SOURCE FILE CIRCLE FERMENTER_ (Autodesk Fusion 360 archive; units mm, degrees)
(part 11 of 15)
sketch "Schizzo6" plane through (170, 0, 0) normal (1, 0, 0) x axis (0, 1, 0)
  line L1 (-85.9, 154.9) -> (-85.9, 164.9)
  curve K1 (-65, 134) -> (-85.9, 154.9)
  line L2 (65, 134) -> (-65, 134)
  curve K2 (85.9, 154.9) -> (65, 134)
  line L3 (85.9, 164.9) -> (85.9, 154.9)
  curve K3 (85.9, 164.9) -> (65, 185.8)
  line L4 (-65, 185.8) -> (65, 185.8)
  curve K4 (-65, 185.8) -> (-85.9, 164.9)
  line L5 (-22.5, 172.4) -> (-72.5, 172.4)
  line L6 (-22.5, 147.4) -> (-22.5, 172.4)
  line L7 (-72.5, 147.4) -> (-22.5, 147.4)
  line L8 (-72.5, 172.4) -> (-72.5, 147.4)
  line L9 (-77.9, 164.9) -> (-77.9, 154.9)
  line L10 (65, 177.8) -> (-65, 177.8)
  line L11 (65, 142) -> (-65, 142)
  line L12 (-77.9, 159.9) -> (-22.5, 159.9)
  curve K5 (-65, 177.8) -> (-77.9, 164.9)
  line L13 (-47.5, 147.4) -> (-47.5, 172.4)
  curve K6 (-71.9336, 172.3394) -> (-71.9423, 172.3232)
  line L14 (-72.5, 164.9) -> (-72.5, 154.9)
  curve K7 (-72.0707, 171.9774) -> (-72.5, 164.9)
  curve K8 (-65, 172.4) -> (-72.0707, 171.9774)
  line L15 (65, 172.4) -> (-65, 172.4)
  curve K9 (-22.9293, 171.9774) -> (-22.5, 164.9)
  curve K10 (-30, 172.4) -> (-22.9293, 171.9774)
  curve K11 (-72.0707, 147.8226) -> (-72.5, 154.9)
  curve K12 (-65, 147.4) -> (-72.0707, 147.8226)
  curve K13 (-30, 147.4) -> (-22.9293, 147.8226)
  curve K14 (-22.9293, 147.8226) -> (-22.5, 154.9)
  circle C1 centre (60, 159.9) radius 3.5
  circle C2 centre (81.9, 159.9) radius 1.75
  circle C3 centre (0, 181.8) radius 1.75
  circle C4 centre (0, 138) radius 1.75
  circle C5 centre (-81.9, 159.9) radius 1.75
  point P25 (-22.5, 159.9)
  point P26 (-77.9, 159.9)
  point P34 (-47.5, 172.4)
  point P35 (-47.5, 147.4)
  point P30 (-72.5, 164.9)
  point P36 (-22.5, 164.9)
  point P31 (-72.0707, 171.9774)
  point P37 (-22.9293, 171.9774)
  point P32 (-65, 172.4)
  point P38 (-30, 172.4)
  point P39 (-72.5, 154.9)
  point P40 (-72.0707, 147.8226)
  point P41 (-65, 147.4)
  point P44 (-22.5, 154.9)
  point P42 (-22.9293, 147.8226)
  point P43 (-30, 147.4)
  point P16 (-22.5, 172.4)
  point P17 (-22.5, 147.4)
  horizontal L5
  vertical L6
  horizontal L7
  vertical L8
  midpoint L6 P25
  midpoint L9 P26
  horizontal L12
  midpoint L5 P34
  midpoint L7 P35
  symmetric P30 L13 P36
  symmetric P31 L13 P37
  symmetric P32 L13 P38
  symmetric L13 K7 K9
  symmetric L13 K8 K10
  symmetric L12 P30 P39
  symmetric L12 P31 P40
  symmetric L12 P32 P41
  symmetric L12 K7 K11
  symmetric L12 K8 K12
  symmetric L12 P36 P44
  symmetric L12 P37 P42
  symmetric L12 K9 K14
  symmetric L12 P38 P43
  symmetric L12 K10 K13
  dimension "d1506" distance P16 P17 = 25
  dimension "d1507" distance L6 L8 = 50
  dimension "d1508" distance L8 L9 = 5.4
  dimension "d1509" = 5.4
extrude "Estrusione3" cut sketch "Schizzo6" profile of L5 L6 L7 L8 K8 L14 L15 K9 K10 K11 K12 K13 K14 against normal blind 3
fillet "Raccordo1" radius 4
component_insert "Inserimento componente1"
joint "Assembla1" alignAngle 0 alignOffsetX 0 alignOffsetY -12.5 alignOffsetZ 0
offset_faces "FacceDiOffset1" distance 0.5
sketch "Schizzo6" plane through (170, 0, 0) normal (1, 0, 0) x axis (0, 1, 0)
  curve K1 (-71.9729, 151.8273) -> (-72, 154.9)
  line L1 (-72, 164.9) -> (-72, 154.9)
  curve K2 (-72, 164.9) -> (-71.9729, 167.9727)
  curve K3 (-71.9729, 167.9727) -> (-68.0604, 171.8773)
  curve K4 (-68.0604, 171.8773) -> (-65, 171.9)
  line L2 (-30, 171.9) -> (-65, 171.9)
  curve K5 (-30, 171.9) -> (-26.9396, 171.8773)
  curve K6 (-26.9396, 171.8773) -> (-23.0271, 167.9727)
  curve K7 (-23.0271, 167.9727) -> (-23, 164.9)
  line L3 (-23, 154.9) -> (-23, 164.9)
  curve K8 (-23, 154.9) -> (-23.0271, 151.8273)
  curve K9 (-23.0271, 151.8273) -> (-26.9396, 147.9227)
  curve K10 (-26.9396, 147.9227) -> (-30, 147.9)
  line L4 (-65, 147.9) -> (-30, 147.9)
  curve K11 (-65, 147.9) -> (-68.0604, 147.9227)
  curve K12 (-68.0604, 147.9227) -> (-71.9729, 151.8273)
  line L5 (-85.9, 154.9) -> (-85.9, 164.9)
  curve K13 (-65, 134) -> (-85.9, 154.9)
  line L6 (65, 134) -> (-65, 134)
  curve K14 (85.9, 154.9) -> (65, 134)
  line L7 (85.9, 164.9) -> (85.9, 154.9)
  curve K15 (85.9, 164.9) -> (65, 185.8)
  line L8 (-65, 185.8) -> (65, 185.8)
  curve K16 (-65, 185.8) -> (-85.9, 164.9)
  line L9 (42.523, 154.9) -> (42.523, 164.9)
  line L10 (-23, 154.9) -> (-23, 164.9)
  line L11 (42.523, 159.9) -> (-23, 159.9)
  circle C1 centre (60, 159.9) radius 3.5
  circle C2 centre (81.9, 159.9) radius 1.75
  circle C3 centre (0, 181.8) radius 1.75
  circle C4 centre (0, 138) radius 1.75
  circle C5 centre (-81.9, 159.9) radius 1.75
  circle C6 centre (-5.2385, 159.9) radius 2.5
  circle C7 centre (9.7615, 159.9) radius 2.5
  circle C8 centre (24.7615, 159.9) radius 2.5
  point P35 (-23, 159.9)
  point P36 (42.523, 159.9)
  point P37 (9.7615, 159.9)
  point P38 (-5.2385, 159.9)
  point P39 (24.7615, 159.9)
  point P40 (-5.2385, 159.9)
  point P41 (9.7615, 159.9)
  point P42 (24.7615, 159.9)
  midpoint L3 P35
  midpoint L9 P36
  midpoint L11 P37
  coincident L11 P38
  coincident L11 P39
  coincident P38 P40
  coincident P37 P41
  coincident P39 P42
  dimension "d1519" distance P37 P38 = 15
  dimension "d1520" distance P37 P39 = 15
  dimension "d1521" diameter C6 = 5
  dimension "d1522" diameter C7 = 5
  dimension "d1523" diameter C8 = 5
extrude "Estrusione4" cut sketch "Schizzo6" profile of C6 C7 C8 against normal blind 3
sketch "Schizzo7" plane through (164, 0, 0) normal (-1, 0, 0) x axis (0, 0, 1)
  line L1 (140.05, -73.65) -> (140.05, -16.65)
  line L2 (177.75, -75.65) -> (142.05, -75.65)
  line L3 (179.75, -16.65) -> (179.75, -73.65)
  line L4 (142.05, -14.65) -> (177.75, -14.65)
  curve K1 (141.3132, 79.0124) -> (139.6916, 76.9033)
  curve K2 (154.9, 81.9) -> (141.3132, 79.0124)
  line L5 (156.9, 81.9) -> (154.9, 81.9)
  line L6 (164.9, 81.9) -> (162.9, 81.9)
  curve K3 (178.4868, 79.0124) -> (164.9, 81.9)
  curve K4 (180.1083, 76.9033) -> (178.4868, 79.0124)
  curve K5 (181.8, 65) -> (180.1083, 76.9033)
  line L7 (181.8, 3) -> (181.8, 65)
  line L8 (181.8, -65) -> (181.8, -3)
  curve K6 (181.2771, -73.5898) -> (181.8, -65)
  curve K7 (179.0826, -78.3954) -> (181.2771, -73.5898)
  curve K8 (164.9, -81.9) -> (179.0826, -78.3954)
  line L9 (162.9, -81.9) -> (164.9, -81.9)
  line L10 (154.9, -81.9) -> (156.9, -81.9)
  curve K9 (140.7174, -78.3954) -> (154.9, -81.9)
  curve K10 (138.5229, -73.5898) -> (140.7174, -78.3954)
  curve K11 (138, -65) -> (138.5229, -73.5898)
  line L11 (138, -3) -> (138, -65)
  line L12 (138, 65) -> (138, 3)
  curve K12 (139.6916, 76.9033) -> (138, 65)
  curve K13 (134.6069, -74.4055) -> (134, -65)
  curve K14 (137.6898, -81.0094) -> (134.6069, -74.4055)
  curve K15 (154.9, -85.9) -> (137.6898, -81.0094)
  line L13 (164.9, -85.9) -> (154.9, -85.9)
  curve K16 (182.1102, -81.0094) -> (164.9, -85.9)
  curve K17 (185.1931, -74.4056) -> (182.1102, -81.0094)
  curve K18 (185.8, -65) -> (185.1931, -74.4056)
  line L14 (185.8, 65) -> (185.8, -65)
  curve K19 (183.6203, 78.818) -> (185.8, 65)
  curve K20 (181.2032, 81.9485) -> (183.6203, 78.818)
  curve K21 (164.9, 85.9) -> (181.2032, 81.9485)
  line L15 (154.9, 85.9) -> (164.9, 85.9)
  curve K22 (138.5968, 81.9485) -> (154.9, 85.9)
  curve K23 (136.1797, 78.818) -> (138.5968, 81.9485)
  curve K24 (134, 65) -> (136.1797, 78.818)
  line L16 (134, -65) -> (134, 65)
  line L17 (144.6716, -75.65) -> (144.6716, -14.65)
  line L18 (175.5614, -75.65) -> (144.6716, -75.65)
  line L19 (175.5614, -14.65) -> (175.5614, -75.65)
  line L20 (144.6716, -14.65) -> (175.5614, -14.65)
  line L21 (181.8, -9.65) -> (138, -9.65)
  circle C1 centre (177.25, -73.15) radius 1
  circle C2 centre (177.25, -17.15) radius 1
  circle C3 centre (142.55, -17.15) radius 1
  circle C4 centre (142.55, -73.15) radius 1
  arc A1 centre (142.05, -16.65) radius 2 clockwise from (140.05, -16.65) to (142.05, -14.65)
  arc A2 centre (142.05, -73.65) radius 2 clockwise from (142.05, -75.65) to (140.05, -73.65)
  arc A3 centre (177.75, -73.65) radius 2 clockwise from (179.75, -73.65) to (177.75, -75.65)
  arc A4 centre (177.75, -16.65) radius 2 clockwise from (177.75, -14.65) to (179.75, -16.65)
  arc A5 centre (159.9, 81.9) radius 3 clockwise from (162.9, 81.9) to (156.9, 81.9)
  arc A6 centre (181.8, 0) radius 3 clockwise from (181.8, -3) to (181.8, 3)
  arc A7 centre (159.9, -81.9) radius 3 clockwise from (156.9, -81.9) to (162.9, -81.9)
  arc A8 centre (138, 0) radius 3 clockwise from (138, 3) to (138, -3)
  circle C5 centre (159.9, 81.9) radius 1.75
  circle C6 centre (159.9, -81.9) radius 1.75
  circle C7 centre (138, 0) radius 1.75
  circle C8 centre (181.8, 0) radius 1.75
  point P66 (138, -9.65)
  point P67 (181.8, -9.65)
  coincident L11 P66
  coincident L8 P67
  perpendicular L8 L21
  dimension "d1526" distance L4 L21 = 5
extrude "Estrusione5" new body sketch "Schizzo7" profile of A1 L1 A2 L2 A3 L3 A4 L4 L8 K6 K7 K8 L9 A7 L10 K9 K10 K11 L11 L18 L20 L21 to an object
combine "Combina1"
extrude "Estrusione6" new body of existing geometry blind 4
combine "Combina2"
sketch "Schizzo6" plane through (160, 0, 0) normal (-1, 0, 0) x axis (0, -1, 0)
  line L1 (14.65, 177.75) -> (14.65, 142.05)
  line L2 (73.65, 179.75) -> (16.65, 179.75)
  line L3 (75.65, 142.05) -> (75.65, 177.75)
  line L4 (16.65, 140.05) -> (73.65, 140.05)
  line L5 (9.65, 138) -> (9.65, 181.8)
  line L6 (3, 138) -> (9.65, 138)
  line L7 (-65, 138) -> (-3, 138)
  curve K1 (-76.9033, 139.6916) -> (-65, 138)
  curve K2 (-79.0124, 141.3132) -> (-76.9033, 139.6916)
  curve K3 (-81.9, 154.9) -> (-79.0124, 141.3132)
  line L8 (-81.9, 156.9) -> (-81.9, 154.9)
  line L9 (-81.9, 164.9) -> (-81.9, 162.9)
  curve K4 (-79.0124, 178.4868) -> (-81.9, 164.9)
  curve K5 (-76.9033, 180.1084) -> (-79.0124, 178.4868)
  curve K6 (-65, 181.8) -> (-76.9033, 180.1084)
  line L10 (-3, 181.8) -> (-65, 181.8)
  line L11 (9.65, 181.8) -> (3, 181.8)
  curve K7 (74.4055, 134.6069) -> (65, 134)
  curve K8 (81.0094, 137.6898) -> (74.4055, 134.6069)
  curve K9 (85.9, 154.9) -> (81.0094, 137.6898)
  line L12 (85.9, 164.9) -> (85.9, 154.9)
  curve K10 (81.0094, 182.1102) -> (85.9, 164.9)
  curve K11 (74.4056, 185.1931) -> (81.0094, 182.1102)
  curve K12 (65, 185.8) -> (74.4056, 185.1931)
  line L13 (-65, 185.8) -> (65, 185.8)
  curve K13 (-78.818, 183.6203) -> (-65, 185.8)
  curve K14 (-81.9485, 181.2032) -> (-78.818, 183.6203)
  curve K15 (-85.9, 164.9) -> (-81.9485, 181.2032)
  line L14 (-85.9, 154.9) -> (-85.9, 164.9)
  curve K16 (-81.9485, 138.5968) -> (-85.9, 154.9)
  curve K17 (-78.818, 136.1797) -> (-81.9485, 138.5968)
  curve K18 (-65, 134) -> (-78.818, 136.1797)
  line L15 (65, 134) -> (-65, 134)
  line L16 (14.65, 142.05) -> (75.65, 142.05)
  line L17 (74.4679, 177.75) -> (75.65, 177.75)
  line L18 (14.65, 177.75) -> (74.4679, 177.75)
  arc A1 centre (16.65, 177.75) radius 2 clockwise from (14.65, 177.75) to (16.65, 179.75)
  arc A2 centre (73.65, 177.75) radius 2 clockwise from (73.65, 179.75) to (75.65, 177.75)
  arc A3 centre (73.65, 142.05) radius 2 clockwise from (75.65, 142.05) to (73.65, 140.05)
  arc A4 centre (16.65, 142.05) radius 2 clockwise from (16.65, 140.05) to (14.65, 142.05)
  arc A5 centre (0, 138) radius 3 clockwise from (-3, 138) to (3, 138)
  arc A6 centre (-81.9, 159.9) radius 3 clockwise from (-81.9, 162.9) to (-81.9, 156.9)
  arc A7 centre (0, 181.8) radius 3 clockwise from (3, 181.8) to (-3, 181.8)
  circle C1 centre (-81.9, 159.9) radius 1.75
  circle C2 centre (81.9, 159.9) radius 1.75
  circle C3 centre (0, 138) radius 1.75
  circle C4 centre (0, 181.8) radius 1.75
  point P9 (75.65, 142.05)
  point P50 (75.65, 142.05)
  point P2 (14.65, 142.05)
  point P51 (14.65, 142.05)
  point P7 (75.65, 177.75)
  point P52 (75.65, 177.75)
  point P3 (14.65, 177.75)
  point P54 (14.65, 177.75)
  coincident P9 P50
  coincident P2 P51
  coincident P7 P52
  perpendicular L1 L17
  coincident P3 P54
extrude "Estrusione4" new body sketch "Schizzo6" profile of A1 L2 A2 A3 L4 A4 L16 L17 L18 against normal blind 3.8
combine "Combina3"
offset_faces "FacceDiOffset1" distance -0.2
fillet "Raccordo1" radius 1 2 2
fillet "Raccordo2" radius 1
sketch "Schizzo1" plane through (160, 0, 0) normal (-1, 0, 0) x axis (0, -1, 0)
  curve K1 (86.4, 164.9) -> (65, 186.3)
  line L1 (86.4, 154.9) -> (86.4, 164.9)
  curve K2 (65, 133.5) -> (86.4, 154.9)
  line L2 (-65, 133.5) -> (65, 133.5)
  curve K3 (-86.4, 154.9) -> (-65, 133.5)
  line L3 (-86.4, 164.9) -> (-86.4, 154.9)
  curve K4 (-65, 186.3) -> (-86.4, 164.9)
  line L4 (65, 186.3) -> (-65, 186.3)
  line L5 (-89.2, 154.9) -> (-89.2, 164.9)
  curve K5 (-89.2, 154.9) -> (-65, 130.7)
  line L6 (65, 130.7) -> (-65, 130.7)
  curve K6 (65, 130.7) -> (89.2, 154.9)
  line L7 (89.2, 164.9) -> (89.2, 154.9)
  curve K7 (65, 189.1) -> (89.2, 164.9)
  line L8 (-65, 189.1) -> (65, 189.1)
  curve K8 (-89.2, 164.9) -> (-65, 189.1)
  curve K9 (90, 154.9) -> (65, 129.9)
  line L9 (90, 164.9) -> (90, 154.9)
  curve K10 (90, 164.9) -> (65, 189.9)
  line L10 (65, 189.9) -> (-65, 189.9)
  curve K11 (-65, 189.9) -> (-90, 164.9)
  line L11 (-90, 154.9) -> (-90, 164.9)
  curve K12 (-65, 129.9) -> (-90, 154.9)
  line L12 (65, 129.9) -> (-65, 129.9)
  line L13 (88.4, 164.9) -> (88.4, 154.9)
  curve K13 (88.4, 164.9) -> (65, 188.3)
  line L14 (65, 188.3) -> (-65, 188.3)
  curve K14 (-65, 188.3) -> (-88.4, 164.9)
  line L15 (-88.4, 154.9) -> (-88.4, 164.9)
  curve K15 (-65, 131.5) -> (-88.4, 154.9)
  line L16 (65, 131.5) -> (-65, 131.5)
  curve K16 (88.4, 154.9) -> (65, 131.5)
  dimension "d1542" = 1.6
extrude "Estrusione1" new body sketch "Schizzo1" profile of L5 K5 L6 K6 L7 K7 L8 K8 K9 L9 K10 L10 K11 L11 K12 L12 K13 L13 K16 L14 K15 K14 L15 L16 along normal blind 160
work_plane "Piano di lavoro1"
split "Dividi1"
remove_body "RimuoviCorpo1"
work_plane "Piano di lavoro2"
split "Dividi2"
remove_body "RimuoviCorpo2"
sketch "Schizzo7" plane through (0, 0, 0) normal (0, 1, 0) x axis (-1, 0, 0)
  line L1 (0, 131.5) -> (0, 129.9)
  line L2 (-160, 131.5) -> (0, 131.5)
  line L3 (-160, 129.9) -> (-160, 131.5)
  line L4 (0, 129.9) -> (-160, 129.9)
  line L5 (-160, 164.9) -> (-160, 186.3)
  line L6 (-160, 154.9) -> (-160, 164.9)
  line L7 (-160, 133.5) -> (-160, 154.9)
  line L8 (-160, 154.9) -> (-160, 133.5)
  line L9 (-160, 164.9) -> (-160, 154.9)
  line L10 (-160, 186.3) -> (-160, 164.9)
  line L11 (-160, 154.9) -> (-160, 164.9)
  line L12 (-160, 154.9) -> (-160, 130.7)
  line L13 (-160, 130.7) -> (-160, 154.9)
  line L14 (-160, 164.9) -> (-160, 154.9)
  line L15 (-160, 189.1) -> (-160, 164.9)
  line L16 (-160, 164.9) -> (-160, 189.1)
  line L17 (-160, 176.75) -> (-160, 143.05)
  line L18 (-160, 177.75) -> (-160, 176.75)
  line L19 (-160, 177.75) -> (-160, 176.75)
  line L20 (-160, 143.05) -> (-160, 176.75)
  line L21 (-160, 143.05) -> (-160, 142.05)
  line L22 (-160, 143.05) -> (-160, 142.05)
  line L23 (-160, 140) -> (-160, 179.8)
  line L24 (-160, 140) -> (-160, 138)
  line L25 (-160, 138.75) -> (-160, 138)
  line L26 (-160, 141) -> (-160, 138.75)
  line L27 (-160, 138.75) -> (-160, 138)
  line L28 (-160, 139.6916) -> (-160, 138)
  line L29 (-160, 141.3132) -> (-160, 139.6916)
  line L30 (-160, 154.9) -> (-160, 141.3132)
  line L31 (-160, 156.027) -> (-160, 154.9)
  line L32 (-160, 156.9953) -> (-160, 156.027)
  line L33 (-160, 162.8047) -> (-160, 156.9953)
  line L34 (-160, 163.773) -> (-160, 162.8047)
  line L35 (-160, 164.9) -> (-160, 163.773)
  line L36 (-160, 178.4868) -> (-160, 164.9)
  line L37 (-160, 180.1084) -> (-160, 178.4868)
  line L38 (-160, 181.8) -> (-160, 180.1084)
  line L39 (-160, 181.8) -> (-160, 181.05)
  line L40 (-160, 181.05) -> (-160, 178.8)
  line L41 (-160, 181.8) -> (-160, 181.05)
  line L42 (-160, 181.8) -> (-160, 179.8)
  line L43 (-160, 158.15) -> (-160, 161.65)
  line L44 (-160, 158.15) -> (-160, 161.65)
  line L45 (-160, 136.25) -> (-160, 139.75)
  line L46 (-160, 180.05) -> (-160, 183.55)
  line L47 (-160, 134.6069) -> (-160, 134)
  line L48 (-160, 137.6898) -> (-160, 134.6069)
  line L49 (-160, 154.9) -> (-160, 137.6898)
  line L50 (-160, 164.9) -> (-160, 154.9)
  line L51 (-160, 182.1102) -> (-160, 164.9)
  line L52 (-160, 185.1931) -> (-160, 182.1102)
  line L53 (-160, 185.8) -> (-160, 185.1931)
  line L54 (-160, 183.6203) -> (-160, 185.8)
  line L55 (-160, 181.2032) -> (-160, 183.6203)
  line L56 (-160, 164.9) -> (-160, 181.2032)
  line L57 (-160, 154.9) -> (-160, 164.9)
  line L58 (-160, 138.5968) -> (-160, 154.9)
  line L59 (-160, 136.1797) -> (-160, 138.5968)
  line L60 (-160, 134) -> (-160, 136.1797)
  line L61 (-151.2986, 138) -> (-160, 138)
  curve K1 (-156, 138) -> (-160, 138)
  curve K2 (-152.5, 134.75) -> (-156, 138)
  curve K3 (-149, 131.5) -> (-152.5, 134.75)
  curve K4 (-145, 131.5) -> (-149, 131.5)
  curve K5 (-145, 131.5) -> (-160, 138)
  point P19 (-160, 138)
  point P51 (-160, 138)
  point P53 (-156, 138)
  point P55 (-149, 131.5)
  point P56 (-145, 131.5)
  coincident P19 P51
  perpendicular L13 L61
  coincident L61 P53
  coincident L2 P55
  coincident L2 P56
  equal K2 K3
  parallel K2 K3
  dimension "d1545" distance L2 L61 = 6.5
  dimension "d1546" distance P51 P53 = 4
  dimension "d1547" distance P55 P56 = 4 (= "d1546")
  dimension "d1548" distance P51 P56 = 15
sweep "Sweep1" sketch "Schizzo7" TwistAngle 0 TaperAngle 0
combine "Combina1"
sketch "Schizzo3" plane through (160, 0, 0) normal (-1, 0, 0) x axis (0, -1, 0)
  line L1 (14.45, 176.75) -> (14.45, 143.05)
  line L2 (74.85, 177.75) -> (15.45, 177.75)
  line L3 (75.85, 143.05) -> (75.85, 176.75)
  line L4 (15.45, 142.05) -> (74.85, 142.05)
  line L5 (9.65, 140) -> (9.65, 179.8)
  line L6 (3.873, 138) -> (7.65, 138)
  line L7 (-65, 138) -> (-3.873, 138)
  curve K1 (-76.9033, 139.6916) -> (-65, 138)
  curve K2 (-79.0124, 141.3132) -> (-76.9033, 139.6916)
  curve K3 (-81.9, 154.9) -> (-79.0124, 141.3132)
  line L8 (-81.9, 156.027) -> (-81.9, 154.9)
  line L9 (-81.9, 164.9) -> (-81.9, 163.773)
  curve K4 (-79.0124, 178.4868) -> (-81.9, 164.9)
  curve K5 (-76.9033, 180.1084) -> (-79.0124, 178.4868)
  curve K6 (-65, 181.8) -> (-76.9033, 180.1084)
  line L10 (-3.873, 181.8) -> (-65, 181.8)
  line L11 (7.65, 181.8) -> (3.873, 181.8)
  curve K7 (74.4055, 134.6069) -> (65, 134)
  curve K8 (81.0094, 137.6898) -> (74.4055, 134.6069)
  curve K9 (85.9, 154.9) -> (81.0094, 137.6898)
  line L12 (85.9, 164.9) -> (85.9, 154.9)
  curve K10 (81.0094, 182.1102) -> (85.9, 164.9)
  curve K11 (74.4056, 185.1931) -> (81.0094, 182.1102)
  curve K12 (65, 185.8) -> (74.4056, 185.1931)
  line L13 (-65, 185.8) -> (65, 185.8)
  curve K13 (-78.818, 183.6203) -> (-65, 185.8)
  curve K14 (-81.9485, 181.2032) -> (-78.818, 183.6203)
  curve K15 (-85.9, 164.9) -> (-81.9485, 181.2032)
  line L14 (-85.9, 154.9) -> (-85.9, 164.9)
  curve K16 (-81.9485, 138.5968) -> (-85.9, 154.9)
  curve K17 (-78.818, 136.1797) -> (-81.9485, 138.5968)
  curve K18 (-65, 134) -> (-78.818, 136.1797)
  line L15 (65, 134) -> (-65, 134)
  line L16 (77.9, 159.9) -> (85.9, 159.9)
  arc A1 centre (15.45, 176.75) radius 1 clockwise from (14.45, 176.75) to (15.45, 177.75)
  arc A2 centre (74.85, 176.75) radius 1 clockwise from (74.85, 177.75) to (75.85, 176.75)
  arc A3 centre (74.85, 143.05) radius 1 clockwise from (75.85, 143.05) to (74.85, 142.05)
  arc A4 centre (15.45, 143.05) radius 1 clockwise from (15.45, 142.05) to (14.45, 143.05)
  arc A5 centre (7.65, 140) radius 2 clockwise from (9.65, 140) to (7.65, 138)
  arc A6 centre (3.873, 139) radius 1 clockwise from (3.873, 138) to (2.9047, 138.75)
  arc A7 centre (0, 138) radius 3 clockwise from (-2.9047, 138.75) to (2.9047, 138.75)
  arc A8 centre (-3.873, 139) radius 1 clockwise from (-2.9047, 138.75) to (-3.873, 138)
  arc A9 centre (-80.9, 156.027) radius 1 clockwise from (-81.9, 156.027) to (-81.15, 156.9953)
  arc A10 centre (-81.9, 159.9) radius 3 clockwise from (-81.15, 162.8047) to (-81.15, 156.9953)
  arc A11 centre (-80.9, 163.773) radius 1 clockwise from (-81.15, 162.8047) to (-81.9, 163.773)
  arc A12 centre (-3.873, 180.8) radius 1 clockwise from (-3.873, 181.8) to (-2.9047, 181.05)
  arc A13 centre (0, 181.8) radius 3 clockwise from (2.9047, 181.05) to (-2.9047, 181.05)
  arc A14 centre (3.873, 180.8) radius 1 clockwise from (2.9047, 181.05) to (3.873, 181.8)
  arc A15 centre (7.65, 179.8) radius 2 clockwise from (7.65, 181.8) to (9.65, 179.8)
  circle C1 centre (-81.9, 159.9) radius 1.75
  circle C2 centre (81.9, 159.9) radius 1.75
  circle C3 centre (0, 138) radius 1.75
  circle C4 centre (0, 181.8) radius 1.75
  circle C5 centre (81.9, 159.9) radius 4
  point P67 (85.9, 159.9)
  point P68 (77.9, 159.9)
  concentric C2 C5
  midpoint L12 P67
  coincident C5 P68
  perpendicular L12 L16
  dimension "d1555" diameter C5 = 8
extrude "Estrusione2" add sketch "Schizzo3" profile of C2 C5 L16 along normal blind 5
extrude "Estrusione3" cut sketch "Schizzo3" profile of C2 L16 along normal blind 8.08
sketch "Schizzo4" plane through (155, 0, 0) normal (-1, 0, 0) x axis (0, -1, 0)
  line L1 (83.5416, 156.2524) -> (83.5416, 159.2937)
  line L2 (77.9, 159.9) -> (80.15, 159.9)
  arc A1 centre (81.9, 159.9) radius 1.75 clockwise from (83.5416, 159.2937) to (80.15, 159.9)
  arc A2 centre (81.9, 159.9) radius 4 clockwise from (83.5416, 156.2524) to (77.9, 159.9)
  circle C1 centre (81.9, 159.9) radius 4
extrude "Estrusione4" cut sketch "Schizzo4" profile of L1 A1 L2 C1 along normal blind 5.997
sketch "Schizzo5" plane through (160, 0, 0) normal (-1, 0, 0) x axis (0, -1, 0)
  line L1 (14.45, 176.75) -> (14.45, 143.05)
  line L2 (74.85, 177.75) -> (15.45, 177.75)
  line L3 (75.85, 143.05) -> (75.85, 176.75)
  line L4 (15.45, 142.05) -> (74.85, 142.05)
  line L5 (9.65, 140) -> (9.65, 179.8)
  line L6 (3.873, 138) -> (7.65, 138)
  line L7 (-65, 138) -> (-3.873, 138)
  curve K1 (-76.9033, 139.6916) -> (-65, 138)
  curve K2 (-79.0124, 141.3132) -> (-76.9033, 139.6916)
  curve K3 (-81.9, 154.9) -> (-79.0124, 141.3132)
  line L8 (-81.9, 156.027) -> (-81.9, 154.9)
  line L9 (-81.9, 164.9) -> (-81.9, 163.773)
  curve K4 (-79.0124, 178.4868) -> (-81.9, 164.9)
  curve K5 (-76.9033, 180.1084) -> (-79.0124, 178.4868)
  curve K6 (-65, 181.8) -> (-76.9033, 180.1084)
  line L10 (-3.873, 181.8) -> (-65, 181.8)
  line L11 (7.65, 181.8) -> (3.873, 181.8)
  curve K7 (74.4055, 134.6069) -> (65, 134)
  curve K8 (81.0094, 137.6898) -> (74.4055, 134.6069)
  curve K9 (85.9, 154.9) -> (81.0094, 137.6898)
  line L12 (85.9, 164.9) -> (85.9, 154.9)
  curve K10 (81.0094, 182.1102) -> (85.9, 164.9)
  curve K11 (74.4056, 185.1931) -> (81.0094, 182.1102)
  curve K12 (65, 185.8) -> (74.4056, 185.1931)
  line L13 (-65, 185.8) -> (65, 185.8)
  curve K13 (-78.818, 183.6203) -> (-65, 185.8)
  curve K14 (-81.9485, 181.2032) -> (-78.818, 183.6203)
  curve K15 (-85.9, 164.9) -> (-81.9485, 181.2032)
  line L14 (-85.9, 154.9) -> (-85.9, 164.9)
  curve K16 (-81.9485, 138.5968) -> (-85.9, 154.9)
  curve K17 (-78.818, 136.1797) -> (-81.9485, 138.5968)
  curve K18 (-65, 134) -> (-78.818, 136.1797)
  line L15 (65, 134) -> (-65, 134)
  line L16 (0, 142) -> (0, 134)
  arc A1 centre (15.45, 176.75) radius 1 clockwise from (14.45, 176.75) to (15.45, 177.75)
  arc A2 centre (74.85, 176.75) radius 1 clockwise from (74.85, 177.75) to (75.85, 176.75)
  arc A3 centre (74.85, 143.05) radius 1 clockwise from (75.85, 143.05) to (74.85, 142.05)
  arc A4 centre (15.45, 143.05) radius 1 clockwise from (15.45, 142.05) to (14.45, 143.05)
  arc A5 centre (7.65, 140) radius 2 clockwise from (9.65, 140) to (7.65, 138)
  arc A6 centre (3.873, 139) radius 1 clockwise from (3.873, 138) to (2.9047, 138.75)
  arc A7 centre (0, 138) radius 3 clockwise from (-2.9047, 138.75) to (2.9047, 138.75)
  arc A8 centre (-3.873, 139) radius 1 clockwise from (-2.9047, 138.75) to (-3.873, 138)
  arc A9 centre (-80.9, 156.027) radius 1 clockwise from (-81.9, 156.027) to (-81.15, 156.9953)
  arc A10 centre (-81.9, 159.9) radius 3 clockwise from (-81.15, 162.8047) to (-81.15, 156.9953)
  arc A11 centre (-80.9, 163.773) radius 1 clockwise from (-81.15, 162.8047) to (-81.9, 163.773)
  arc A12 centre (-3.873, 180.8) radius 1 clockwise from (-3.873, 181.8) to (-2.9047, 181.05)
  arc A13 centre (0, 181.8) radius 3 clockwise from (2.9047, 181.05) to (-2.9047, 181.05)
  arc A14 centre (3.873, 180.8) radius 1 clockwise from (2.9047, 181.05) to (3.873, 181.8)
  arc A15 centre (7.65, 179.8) radius 2 clockwise from (7.65, 181.8) to (9.65, 179.8)
  circle C1 centre (-81.9, 159.9) radius 1.75
  circle C2 centre (81.9, 159.9) radius 1.75
  circle C3 centre (0, 138) radius 1.75
  circle C4 centre (0, 181.8) radius 1.75
  circle C5 centre (0, 138) radius 1.75
  circle C6 centre (0, 138) radius 4
  point P68 (0, 134)
  point P69 (0, 142)
  concentric A7 C6
  midpoint L15 P68
  coincident C6 P69
  perpendicular L15 L16
  dimension "d1562" diameter C6 = 8
extrude "Estrusione5" cut sketch "Schizzo5" profile of L6 A6 A7 C3 C5 C6 L16 along normal blind 10
remove_body "RimuoviCorpo3"
extrude "Estrusione6" add sketch "Schizzo5" profile of L6 A6 A7 C3 C5 C6 L16 along normal blind 5
fillet "Raccordo1" radius 3 1
fillet "Raccordo2" radius 0.5
mirror "Specchio1" mirrorStitchTolerance 0.1
revolve "Rivoluzione1" AlongAngle 360
revolve "Rivoluzione2" AlongAngle 360
copy_paste_bodies "CopiaIncollaCorpi"
move "Sposta1"
mirror "Specchio2" mirrorStitchTolerance 0.1
combine "Combina2"
extrude "Estrusione7" add of existing geometry blind 0.2
extrude "Estrusione8" add of existing geometry blind 2.2
extrude "Estrusione9" add of existing geometry blind 2.2
sketch "Schizzo6" plane through (0, 0, 0) normal (-1, 0, 0) x axis (0, -1, 0)
  line L1 (-64.9968, 129.9) -> (-65, 129.9)
  curve K1 (-54, 116.8) -> (-64.9968, 129.9)
  line L2 (-54, 115) -> (-54, 116.8)
  line L3 (-52, 115) -> (-54, 115)
  line L4 (-52, 116.8) -> (-52, 115)
  curve K2 (-54.3995, 129.9) -> (-52, 116.8)
  line L5 (54.3995, 129.9) -> (-54.3995, 129.9)
  curve K3 (52, 116.8) -> (54.3995, 129.9)
  line L6 (52, 115) -> (52, 116.8)
  line L7 (54, 115) -> (52, 115)
  line L8 (54, 116.8) -> (54, 115)
  curve K4 (64.9968, 129.9) -> (54, 116.8)
  line L9 (65, 129.9) -> (64.9968, 129.9)
  curve K5 (90, 154.9) -> (65, 129.9)
  line L10 (90, 159.9) -> (90, 154.9)
  line L11 (88.4, 159.9) -> (90, 159.9)
  line L12 (88.4, 154.9) -> (88.4, 159.9)
  curve K6 (65, 131.5) -> (88.4, 154.9)
  line L13 (-65, 131.5) -> (65, 131.5)
  curve K7 (-65, 131.5) -> (-88.4, 154.9)
  line L14 (-88.4, 159.9) -> (-88.4, 154.9)
  line L15 (-90, 159.9) -> (-88.4, 159.9)
  line L16 (-90, 154.9) -> (-90, 159.9)
  curve K8 (-90, 154.9) -> (-65, 129.9)
  line L17 (54.3995, 129.9) -> (64.9968, 129.9)
  point P14 (64.9968, 129.9)
  point P26 (64.9968, 129.9)
  point P9 (54.3995, 129.9)
  point P27 (54.3995, 129.9)
  coincident P14 P26
  coincident P9 P27
sweep "Sweep1" sketch "Schizzo6" TwistAngle 0 TaperAngle 0
sketch "Schizzo7" plane through (0, 0, 0) normal (-1, 0, 0) x axis (0, -1, 0)
  line L1 (-64.9968, 129.9) -> (-65, 129.9)
  curve K1 (-54, 116.8) -> (-64.9968, 129.9)
  line L2 (-54, 115) -> (-54, 116.8)
  line L3 (-52, 115) -> (-54, 115)
  line L4 (-52, 116.8) -> (-52, 115)
  curve K2 (-54.3995, 129.9) -> (-52, 116.8)
  line L5 (54.3995, 129.9) -> (-54.3995, 129.9)
  curve K3 (52, 116.8) -> (54.3995, 129.9)
  line L6 (52, 115) -> (52, 116.8)
  line L7 (54, 115) -> (52, 115)
  line L8 (54, 116.8) -> (54, 115)
  curve K4 (64.9968, 129.9) -> (54, 116.8)
  line L9 (65, 129.9) -> (64.9968, 129.9)
  curve K5 (90, 154.9) -> (65, 129.9)
  line L10 (90, 159.9) -> (90, 154.9)
  line L11 (88.4, 159.9) -> (90, 159.9)
  line L12 (88.4, 154.9) -> (88.4, 159.9)
  curve K6 (65, 131.5) -> (88.4, 154.9)
  line L13 (-65, 131.5) -> (65, 131.5)
  curve K7 (-65, 131.5) -> (-88.4, 154.9)
  line L14 (-88.4, 159.9) -> (-88.4, 154.9)
  line L15 (-90, 159.9) -> (-88.4, 159.9)
  line L16 (-90, 154.9) -> (-90, 159.9)
  curve K8 (-90, 154.9) -> (-65, 129.9)
  line L17 (-64.9968, 129.9) -> (64.9968, 129.9)
  line L18 (-52, 115) -> (52, 115)
  point P14 (64.9968, 129.9)
  point P26 (64.9968, 129.9)
  point P3 (-64.9968, 129.9)
  point P27 (-64.9968, 129.9)
  point P11 (52, 115)
  point P28 (52, 115)
  point P6 (-52, 115)
  point P29 (-52, 115)
  coincident P14 P26
  coincident P3 P27
  coincident P11 P28
  coincident P6 P29
extrude "Estrusione10" cut sketch "Schizzo7" profile of K1 L2 L3 L4 K2 L5 K3 L6 L7 L8 K4 L17 L18 against normal blind 225.622
sketch "Schizzo8" plane through (0, 0, 0) normal (-1, 0, 0) x axis (0, -1, 0)
  line L1 (-64.9968, 129.9) -> (-54.3995, 129.9)
  curve K1 (-54, 116.8) -> (-64.9968, 129.9)
  line L2 (-54, 115) -> (-54, 116.8)
  line L3 (-52, 115) -> (-54, 115)
  line L4 (-52, 116.8) -> (-52, 115)
  curve K2 (-54.3995, 129.9) -> (-52, 116.8)
  curve K3 (-54, 116.8) -> (-64.9968, 129.9)
  line L5 (-54, 115) -> (-54, 116.8)
  line L6 (-52, 115) -> (-52, 116.8)
  line L7 (-62.9366, 129.9) -> (-64.9968, 129.9)
  curve K4 (-52, 116.8) -> (-62.9366, 129.9)
  point P3 (-64.9968, 129.9)
  point P13 (-64.9968, 129.9)
  point P14 (-62.9366, 129.9)
  coincident P3 P13
  coincident L1 P14
sweep "Sweep2" sketch "Schizzo8" TwistAngle 0 TaperAngle 0
combine "Combina3"
sketch "Schizzo9" plane through (0, 0, 129.9) normal (0, 0, -1) x axis (1, 0, 0)
  line L1 (0, -54.3995) -> (0, 54.3995)
  line L2 (0, 54.3995) -> (2.2, 54.3995)
  curve K1 (132.9366, -25) -> (95, -62.9366)
  line L3 (132.9366, 25) -> (132.9366, -25)
  curve K2 (95, 62.9366) -> (132.9366, 25)
  line L4 (0, 62.9366) -> (95, 62.9366)
  line L5 (0, 54.3995) -> (0, 62.9366)
  line L6 (2.2, 54.3995) -> (0, 54.3995)
  line L7 (0, -62.9366) -> (0, -54.3995)
  line L8 (0, -62.9366) -> (0, 62.9366)
  line L9 (2.2, -54.3995) -> (0, -54.3995)
  line L10 (95, -54.3995) -> (2.2, -54.3995)
  curve K3 (124.3995, -25) -> (95, -54.3995)
  line L11 (124.3995, 25) -> (124.3995, -25)
  curve K4 (95, 54.3995) -> (124.3995, 25)
  line L12 (2.2, 54.3995) -> (95, 54.3995)
  line L13 (95, -62.9366) -> (0, -62.9366)
  line L14 (2.2, 54.3995) -> (95, 54.3995)
  curve K5 (95, 54.3995) -> (124.3995, 25)
  line L15 (124.3995, 25) -> (124.3995, -25)
  curve K6 (124.3995, -25) -> (95, -54.3995)
  line L16 (95, -54.3995) -> (2.2, -54.3995)
  line L17 (0, -54.3995) -> (2.2, -54.3995)
  circle C1 centre (32, 60) radius 1.75
  circle C2 centre (95, 60) radius 1.75
  circle C3 centre (130, 25) radius 1.75
  circle C4 centre (32, -60) radius 1.75
  circle C5 centre (95, -60) radius 1.75
  circle C6 centre (130, -25) radius 1.75
  point P11 (0, 62.9366)
  point P15 (0, 62.9366)
  point P6 (0, -62.9366)
  point P16 (0, -62.9366)
  coincident P11 P15
  coincident P6 P16
extrude "Estrusione11" cut sketch "Schizzo9" profile of L1 L2 K1 L3 K2 L4 L5 L6 L7 L8 against normal blind 20.311
remove_body "RimuoviCorpo4"
remove_body "RimuoviCorpo5"
remove_body "RimuoviCorpo6"
remove_body "RimuoviCorpo7"
remove_body "RimuoviCorpo8"
remove_body "RimuoviCorpo9"
fillet "Raccordo3" radius 1.5
sketch "Schizzo10" plane through (0, 0, 115) normal (0, 0, -1) x axis (1, 0, 0)
  line L1 (0, 52) -> (0, 54)
  line L2 (95, 52) -> (0, 52)
  line L3 (95, 54) -> (95, 52)
  line L4 (0, 54) -> (95, 54)
  line L5 (122, -25) -> (124, -25)
  curve K1 (95, -52) -> (122, -25)
  line L6 (95, -54) -> (95, -52)
  curve K2 (95, -54) -> (124, -25)
  line L7 (0, -52) -> (95, -52)
  line L8 (122, 25) -> (124, 25)
  line L9 (122, -25) -> (122, 25)
  line L10 (124, -25) -> (122, -25)
  line L11 (124, 25) -> (124, -25)
  curve K3 (122, 25) -> (95, 52)
  line L12 (95, 52) -> (0, 52)
  line L13 (0, -52) -> (0, 52)
  point P3 (0, 52)
  point P19 (0, 52)
  point P11 (0, -52)
  point P20 (0, -52)
  coincident P3 P19
  coincident P11 P20
extrude "Estrusione12" add sketch "Schizzo10" profile of L2 K1 L7 L9 K3 L12 L13 against normal blind 1.6
chamfer "Smusso1" distance 1.8
split "Dividi3"
remove_body "RimuoviCorpo10"
sketch "Schizzo12" plane through (0, 0, 0) normal (-1, 0, 0) x axis (0, -1, 0)
  line L1 (52, 115) -> (0, 115)
  line L2 (0, 116.6) -> (52, 116.6)
  line L3 (65, 154.9) -> (88.4, 154.9)
  line L4 (65, 131.5) -> (65, 154.9)
  line L5 (89.1105, 130.7895) -> (65, 154.9)
  line L6 (0, 136.25) -> (0, 129.9)
  line L7 (0, 142) -> (0, 139.75)
  curve K1 (3.614, 139.7143) -> (6.3246, 138)
  line L8 (65, 138) -> (6.3246, 138)
  curve K2 (81.897, 153.5609) -> (65, 138)
  curve K3 (81.897, 153.5609) -> (80.184, 156.2868)
  line L9 (90, 159.9) -> (85.9, 159.9)
  line L10 (90, 154.9) -> (90, 159.9)
  curve K4 (90, 154.9) -> (65, 129.9)
  line L11 (0, 129.9) -> (65, 129.9)
  line L12 (0, 115) -> (0, 116.6)
  line L13 (52, 116.6) -> (52, 115)
  circle C1 centre (80.2735, 139.6265) radius 6
  arc A1 centre (0, 138) radius 1.75 clockwise from (0, 139.75) to (0, 136.25)
  arc A2 centre (0, 138) radius 4 clockwise from (0, 142) to (3.614, 139.7143)
  arc A3 centre (81.9, 159.9) radius 4 clockwise from (80.184, 156.2868) to (85.9, 159.9)
  circle C2 centre (81.9, 159.9) radius 1.75
  point P10 (80.2735, 139.6265)
  point P7 (65, 154.9)
  horizontal L3
  vertical L4
  coincident L5 P10
  dimension "d1607" angle L3 L5 = 45
  dimension "d1608" diameter C1 = 12
  dimension "d1609" distance P7 P10 = 21.6
extrude "Estrusione13" add sketch "Schizzo12" profile of C1 K2 against normal blind 8
fillet "Raccordo4" radius 5
chamfer "Smusso2" distance 10.4 distance 10.42
sketch "Schizzo13" plane through (0, 0, 0) normal (-1, 0, 0) x axis (0, -1, 0)
  line L1 (52, 115) -> (0, 115)
  line L2 (0, 116.6) -> (52, 116.6)
  line L3 (0, 115) -> (0, 116.6)
  line L4 (52, 116.6) -> (52, 115)
  circle C1 centre (80.2735, 139.6265) radius 2
  dimension "d1616" diameter C1 = 4
extrude "Estrusione14" cut sketch "Schizzo13" profile of C1 against normal blind 4
sketch "Schizzo14" plane through (0, 0, 159.9) normal (0, 0, 1) x axis (-1, 0, 0)
  line L1 (-155.5, 85.9) -> (-160, 85.9)
  line L2 (-151.6713, 85.9) -> (-154.5, 85.9)
  curve K1 (-151.6713, 85.9) -> (-151.1286, 86.06)
  curve K2 (-145, 88.4) -> (-151.1286, 86.06)
  line L3 (0, 88.4) -> (-145, 88.4)
  line L4 (0, 90) -> (0, 88.4)
  line L5 (-160, 90) -> (0, 90)
  line L6 (-160, 85.9) -> (-160, 90)
  line L7 (-160, 90) -> (0, 90)
  line L8 (-76, 80) -> (-80, 80)
  line L9 (-64.3431, 90) -> (-77.1716, 77.1716)
  line L10 (-80, 90) -> (-80, 80)
  line L11 (-95.6569, 90) -> (-82.8284, 77.1716)
  arc A1 centre (-155.5, 85.4) radius 0.5 clockwise from (-155.5, 85.9) to (-155, 85.4)
  arc A2 centre (-154.5, 85.4) radius 0.5 clockwise from (-155, 85.4) to (-154.5, 85.9)
  circle C1 centre (-80, 80) radius 4
  point P16 (-80, 80)
  point P17 (-80, 80)
  point P18 (-76, 80)
  point P19 (-77.1716, 77.1716)
  point P20 (-64.3431, 90)
  point P21 (-80, 90)
  point P22 (-82.8284, 77.1716)
  point P23 (-95.6569, 90)
  point P14 (0, 90)
  coincident P16 P17
  coincident C1 P18
  horizontal L8
  coincident C1 P19
  coincident L5 P20
  tangent C1 L9
  coincident L5 P21
  perpendicular L5 L10
  symmetric P19 L10 P22
  symmetric P20 L10 P23
  dimension "d1619" distance P14 P16 = 80
  dimension "d1620" distance L7 P16 = 10
  dimension "d1621" diameter C1 = 8
  dimension "d1622" angle L7 L9 = 45
extrude "Estrusione15" add sketch "Schizzo14" profile of L3 C1 L9 L11 to an object
fillet "Raccordo6" radius 4
mirror "Specchio3" mirrorStitchTolerance 0.1
sketch "Schizzo15" plane through (160, 0, 0) normal (1, 0, 0) x axis (0, 1, 0)
  line L1 (90, 159.9) -> (85.9, 159.9)
  line L2 (90, 164.9) -> (90, 159.9)
  curve K1 (90, 164.9) -> (65, 189.9)
  line L3 (-65, 189.9) -> (65, 189.9)
  curve K2 (-90, 164.9) -> (-65, 189.9)
  line L4 (-90, 159.9) -> (-90, 164.9)
  line L5 (-85.9, 159.9) -> (-90, 159.9)
  curve K3 (-81.897, 166.2391) -> (-80.184, 163.5132)
  curve K4 (-81.897, 166.2391) -> (-65, 181.8)
  line L6 (-6.3246, 181.8) -> (-65, 181.8)
  curve K5 (-3.614, 180.0857) -> (-6.3246, 181.8)
  curve K6 (3.614, 180.0857) -> (6.3246, 181.8)
  line L7 (65, 181.8) -> (6.3246, 181.8)
  curve K7 (81.897, 166.2391) -> (65, 181.8)
  curve K8 (81.897, 166.2391) -> (80.184, 163.5132)
  circle C1 centre (81.9, 159.9) radius 1.75
  circle C2 centre (0, 181.8) radius 1.75
  circle C3 centre (-81.9, 159.9) radius 1.75
  arc A1 centre (81.9, 159.9) radius 4 clockwise from (85.9, 159.9) to (80.184, 163.5132)
  arc A2 centre (-81.9, 159.9) radius 4 clockwise from (-80.184, 163.5132) to (-85.9, 159.9)
  arc A3 centre (0, 181.8) radius 4 clockwise from (3.614, 180.0857) to (-3.614, 180.0857)
  circle C4 centre (-81.9, 159.9) radius 4
  circle C5 centre (0, 181.8) radius 4
  circle C6 centre (81.9, 159.9) radius 4
  point P14 (-80.184, 163.5132)
  point P19 (3.614, 180.0857)
  concentric C3 C4
  coincident P14 C4
  concentric C2 C5
  coincident P19 C5
  concentric C1 C6
extrude "Estrusione16" cut sketch "Schizzo15" profile of C1 C2 C3 A1 A2 A3 C4 C5 C6 against normal blind 10
fillet "Raccordo7" radius 2
sketch "Schizzo16" plane through (0, 0, 159.9) normal (0, 0, 1) x axis (-1, 0, 0)
  line L1 (-82.8284, 77.1716) -> (-94.0569, 88.4)
  line L2 (-65.9431, 88.4) -> (-77.1716, 77.1716)
  line L3 (-65.1378, 88.4) -> (-64.2863, 88.4)
  line L4 (-95.7137, 88.4) -> (-65.1378, 88.4)
  line L5 (-77.1716, -77.1716) -> (-65.9431, -88.4)
  line L6 (-94.0569, -88.4) -> (-82.8284, -77.1716)
  line L7 (-95.7137, -88.4) -> (-64.2863, -88.4)
  line L8 (-94.0569, 88.4) -> (-65.9431, 88.4)
  line L9 (-65.9431, -88.4) -> (-94.0569, -88.4)
  arc A1 centre (-80, 80) radius 4 clockwise from (-77.1716, 77.1716) to (-82.8284, 77.1716)
  arc A2 centre (-80, -80) radius 4 clockwise from (-82.8284, -77.1716) to (-77.1716, -77.1716)
extrude "Estrusione17" cut sketch "Schizzo16" profile of L1 A1 L2 L3 L4 L5 A2 L6 L7 against normal blind 3
sketch "Schizzo17" plane through (0, 0, 0) normal (-1, 0, 0) x axis (0, -1, 0)
  line L1 (-65, 189.9) -> (65, 189.9)
  curve K1 (-90, 164.9) -> (-65, 189.9)
  line L2 (-90, 159.9) -> (-90, 164.9)
  line L3 (-88.4, 159.9) -> (-90, 159.9)
  line L4 (-88.4, 164.9) -> (-88.4, 159.9)
  curve K2 (-65, 188.3) -> (-88.4, 164.9)
  line L5 (65, 188.3) -> (-65, 188.3)
  curve K3 (65, 188.3) -> (88.4, 164.9)
  line L6 (88.4, 159.9) -> (88.4, 164.9)
  line L7 (90, 159.9) -> (88.4, 159.9)
  line L8 (90, 164.9) -> (90, 159.9)
  curve K4 (90, 164.9) -> (65, 189.9)
  line L9 (88.4, 157.1) -> (88.4, 159.9)
  line L10 (86.4, 157.1) -> (88.4, 157.1)
  line L11 (86.4, 163.1) -> (86.4, 157.1)
  line L12 (88.4, 163.1) -> (86.4, 163.1)
  point P11 (88.4, 159.9)
  point P14 (88.4, 159.9)
  point P18 (88.4, 163.1)
  point P15 (88.4, 157.1)
  point P16 (86.4, 157.1)
  point P17 (86.4, 163.1)
  coincident P11 P14
  perpendicular L7 L9
  perpendicular L9 L10
  perpendicular L10 L11
  coincident L6 P18
  perpendicular L6 L12
  dimension "d1635" distance P14 P15 = 2.8
  dimension "d1636" distance P15 P16 = 2
  dimension "d1637" distance P16 P17 = 6
extrude "Estrusione18" new body sketch "Schizzo17" profile of L6 L9 L10 L11 L12 against normal blind 135
combine "Combina4"
split "Dividi4"
remove_body "RimuoviCorpo11"
sketch "Schizzo18" plane through (0, 0, 156.9) normal (0, 0, 1) x axis (-1, 0, 0)
  line L1 (-82.8284, 77.1716) -> (-94.0569, 88.4)
  line L2 (-65.9431, 88.4) -> (-77.1716, 77.1716)
  line L3 (-94.0569, 88.4) -> (-65.9431, 88.4)
  arc A1 centre (-80, 80) radius 4 clockwise from (-77.1716, 77.1716) to (-82.8284, 77.1716)
extrude "Estrusione19" add sketch "Schizzo18" profile of L1 A1 L2 to an object
extrude "Estrusione20" cut of existing geometry blind -0.2
fillet "Raccordo8" radius 1 2 3
fillet "Raccordo9" radius 5
offset_faces "FacceDiOffset1" distance -0.2
sketch "Schizzo19" plane through (0, 0, 156.9) normal (0, 0, 1) x axis (-1, 0, 0)
  line L1 (-82.8284, 77.1716) -> (-94.0569, 88.4)
  line L2 (-65.9431, 88.4) -> (-77.1716, 77.1716)
  line L3 (-94.0569, 88.4) -> (-65.9431, 88.4)
  line L4 (-65.9431, 88.4) -> (-77.1716, 77.1716)
  line L5 (-94.0569, 88.4) -> (-65.9431, 88.4)
  line L6 (-82.8284, 77.1716) -> (-94.0569, 88.4)
  arc A1 centre (-80, 80) radius 4 clockwise from (-77.1716, 77.1716) to (-82.8284, 77.1716)
  circle C1 centre (-80, 80) radius 2
  circle C2 centre (-80, -80) radius 2
  arc A2 centre (-80, 80) radius 4 clockwise from (-77.1716, 77.1716) to (-82.8284, 77.1716)
  concentric A1 C1
  dimension "d1653" diameter C1 = 4
  dimension "d1654" diameter C2 = 4
extrude "Estrusione21" cut sketch "Schizzo19" profile of C1 C2 against normal blind 4
sketch "Schizzo20" plane through (0, 0, 157.1) normal (0, 0, -1) x axis (1, 0, 0)
  line L1 (0, 88.2) -> (135, 88.2)
  line L2 (0, 86.4) -> (0, 88.2)
  line L3 (67.9431, 86.4) -> (0, 86.4)
  line L4 (77.1716, 77.1716) -> (67.9431, 86.4)
  line L5 (92.0569, 86.4) -> (82.8284, 77.1716)
  line L6 (135, 86.4) -> (92.0569, 86.4)
  line L7 (135, 88.2) -> (135, 86.4)
  arc A1 centre (80, 80) radius 4 clockwise from (82.8284, 77.1716) to (77.1716, 77.1716)
  circle C1 centre (80, 80) radius 1.75
  concentric A1 C1
  dimension "d1657" diameter C1 = 3.5
extrude "Estrusione22" cut sketch "Schizzo20" profile of C1 against normal blind 82.297
work_plane "Piano di lavoro3" AlongDistance -25
sketch "Schizzo21" plane through (0, 0, 182.1) normal (0, 0, -1) x axis (-1, 0, 0)
  circle C1 centre (-80, -80) radius 1.75
  circle C2 centre (-80, -80) radius 3
  concentric C1 C2
  dimension "d1661" diameter C2 = 6
extrude "Estrusione23" cut sketch "Schizzo21" against normal blind 16.929
fillet "Raccordo10" radius 0.5
sketch "Schizzo22" plane through (0, 0, 0) normal (-1, 0, 0) x axis (0, -1, 0)
  line L1 (86.4, 157.1) -> (86.4, 163.1)
  line L2 (88.2, 157.1) -> (86.4, 157.1)
  line L3 (88.2, 159.9) -> (88.2, 157.1)
  line L4 (90, 159.9) -> (88.2, 159.9)
  line L5 (90, 164.9) -> (90, 159.9)
  curve K1 (90, 164.9) -> (65, 189.9)
  line L6 (0, 189.9) -> (65, 189.9)
  line L7 (0, 188.3) -> (0, 189.9)
  line L8 (65, 188.3) -> (0, 188.3)
  curve K2 (65, 188.3) -> (88.4, 164.9)
  line L9 (88.4, 163.1) -> (88.4, 164.9)
  line L10 (49.1556, 159.9) -> (90, 159.9)
  line L11 (86.4, 163.1) -> (88.4, 163.1)
  circle C1 centre (-80.2735, 139.6265) radius 2
  circle C2 centre (80.2735, 139.6265) radius 2
  circle C3 centre (80.2735, 139.6265) radius 6
  circle C4 centre (80.2735, 180.1735) radius 6
  circle C5 centre (80.2735, 139.6265) radius 6
  circle C6 centre (-80.2735, 139.6265) radius 6
  point P6 (90, 159.9)
  point P16 (90, 159.9)
  coincident P6 P16
  perpendicular L5 L10
  concentric C2 C3
  symmetric L10 C3 C4
  dimension "d1666" diameter C3 = 12
extrude "Estrusione24" add sketch "Schizzo22" profile of K2 C4 against normal blind 8
fillet "Raccordo11" radius 5
fillet "Raccordo12" radius 4
sketch "Schizzo23" plane through (0, 0, 0) normal (-1, 0, 0) x axis (0, -1, 0)
  line L1 (86.4, 157.1) -> (86.4, 163.1)
  line L2 (88.2, 157.1) -> (86.4, 157.1)
  line L3 (88.2, 159.9) -> (88.2, 157.1)
  line L4 (90, 159.9) -> (88.2, 159.9)
  line L5 (90, 164.9) -> (90, 159.9)
  curve K1 (90, 164.9) -> (65, 189.9)
  line L6 (0, 189.9) -> (65, 189.9)
  line L7 (0, 188.3) -> (0, 189.9)
  line L8 (65, 188.3) -> (0, 188.3)
  curve K2 (65, 188.3) -> (69.9527, 188.2187)
  curve K3 (69.9527, 188.2187) -> (74.509, 181.8379)
  curve K4 (81.9366, 174.4086) -> (88.3168, 169.8415)
  curve K5 (88.3168, 169.8415) -> (88.4, 164.9)
  line L9 (88.4, 163.1) -> (88.4, 164.9)
  line L10 (86.4, 163.1) -> (88.4, 163.1)
  arc A1 centre (80.2735, 180.1735) radius 6 clockwise from (81.9366, 174.4086) to (74.509, 181.8379)
  circle C1 centre (80.2735, 180.1735) radius 2
  concentric A1 C1
  dimension "d1673" diameter C1 = 4
extrude "Estrusione25" cut sketch "Schizzo23" profile of C1 against normal blind 4
mirror "Specchio4" mirrorStitchTolerance 0.1
sketch "Schizzo24" plane through (0, 0, 0) normal (-1, 0, 0) x axis (0, -1, 0)
  line L1 (86.4, 157.1) -> (86.4, 163.1)
  line L2 (88.2, 157.1) -> (86.4, 157.1)
  line L3 (88.2, 159.9) -> (88.2, 157.1)
  line L4 (90, 159.9) -> (88.2, 159.9)
  line L5 (90, 164.9) -> (90, 159.9)
  curve K1 (90, 164.9) -> (65, 189.9)
  line L6 (-65, 189.9) -> (65, 189.9)
  curve K2 (-90, 164.9) -> (-65, 189.9)
  line L7 (-90, 159.9) -> (-90, 164.9)
  line L8 (-88.2, 159.9) -> (-90, 159.9)
  line L9 (-88.2, 157.1) -> (-88.2, 159.9)
  line L10 (-86.4, 157.1) -> (-88.2, 157.1)
  line L11 (-86.4, 163.1) -> (-86.4, 157.1)
  line L12 (-88.4, 164.9) -> (-88.4, 163.1)
  curve K3 (-88.3168, 169.8415) -> (-88.4, 164.9)
  curve K4 (-81.9366, 174.4086) -> (-88.3168, 169.8415)
  curve K5 (-69.9527, 188.2187) -> (-74.509, 181.8379)
  curve K6 (-65, 188.3) -> (-69.9527, 188.2187)
  line L13 (65, 188.3) -> (-65, 188.3)
  curve K7 (65, 188.3) -> (69.9527, 188.2187)
  curve K8 (69.9527, 188.2187) -> (74.509, 181.8379)
  curve K9 (81.9366, 174.4086) -> (88.3168, 169.8415)
  curve K10 (88.3168, 169.8415) -> (88.4, 164.9)
  line L14 (88.4, 163.1) -> (88.4, 164.9)
  line L15 (0, 166.1601) -> (0, 188.3)
  line L16 (86.4, 163.1) -> (88.4, 163.1)
  line L17 (-88.4, 163.1) -> (-86.4, 163.1)
  circle C1 centre (-80.2735, 180.1735) radius 2
  circle C2 centre (80.2735, 180.1735) radius 2
  arc A1 centre (-80.2735, 180.1735) radius 6 clockwise from (-74.509, 181.8379) to (-81.9366, 174.4086)
  arc A2 centre (80.2735, 180.1735) radius 6 clockwise from (81.9366, 174.4086) to (74.509, 181.8379)
  circle C3 centre (0, 183.9) radius 6
  point P32 (0, 188.3)
  point P34 (0, 183.9)
  midpoint L13 P32
  perpendicular L13 L15
  coincident L15 P34
  tangent L6 C3
  dimension "d1678" diameter C3 = 12
extrude "Estrusione26" add sketch "Schizzo24" profile of L13 C3 against normal blind 8
fillet "Raccordo13" radius 5
fillet "Raccordo14" radius 4
sketch "Schizzo25" plane through (0, 0, 0) normal (-1, 0, 0) x axis (0, -1, 0)
  line L1 (86.4, 157.1) -> (86.4, 163.1)
  line L2 (88.2, 157.1) -> (86.4, 157.1)
  line L3 (88.2, 159.9) -> (88.2, 157.1)
  line L4 (90, 159.9) -> (88.2, 159.9)
  line L5 (90, 164.9) -> (90, 159.9)
  curve K1 (90, 164.9) -> (65, 189.9)
  line L6 (-65, 189.9) -> (65, 189.9)
  curve K2 (-90, 164.9) -> (-65, 189.9)
  line L7 (-90, 159.9) -> (-90, 164.9)
  line L8 (-88.2, 159.9) -> (-90, 159.9)
  line L9 (-88.2, 157.1) -> (-88.2, 159.9)
  line L10 (-86.4, 157.1) -> (-88.2, 157.1)
  line L11 (-86.4, 163.1) -> (-86.4, 157.1)
  line L12 (-88.4, 164.9) -> (-88.4, 163.1)
  curve K3 (-88.3168, 169.8415) -> (-88.4, 164.9)
  curve K4 (-81.9366, 174.4086) -> (-88.3168, 169.8415)
  curve K5 (-69.9527, 188.2187) -> (-74.509, 181.8379)
  curve K6 (-65, 188.3) -> (-69.9527, 188.2187)
  line L13 (-10.9836, 188.3) -> (-65, 188.3)
  line L14 (65, 188.3) -> (10.9836, 188.3)
  curve K7 (65, 188.3) -> (69.9527, 188.2187)
  curve K8 (69.9527, 188.2187) -> (74.509, 181.8379)
  curve K9 (81.9366, 174.4086) -> (88.3168, 169.8415)
  curve K10 (88.3168, 169.8415) -> (88.4, 164.9)
  line L15 (88.4, 163.1) -> (88.4, 164.9)
  line L16 (86.4, 163.1) -> (88.4, 163.1)
  line L17 (-88.4, 163.1) -> (-86.4, 163.1)
  circle C1 centre (-80.2735, 180.1735) radius 2
  circle C2 centre (80.2735, 180.1735) radius 2
  arc A1 centre (-80.2735, 180.1735) radius 6 clockwise from (-74.509, 181.8379) to (-81.9366, 174.4086)
  arc A2 centre (-10.9836, 183.3) radius 5 clockwise from (-10.9836, 188.3) to (-5.9911, 183.5727)
  arc A3 centre (0, 183.9) radius 6 clockwise from (5.9911, 183.5727) to (-5.9911, 183.5727)
  arc A4 centre (10.9836, 183.3) radius 5 clockwise from (5.9911, 183.5727) to (10.9836, 188.3)
  arc A5 centre (80.2735, 180.1735) radius 6 clockwise from (81.9366, 174.4086) to (74.509, 181.8379)
  circle C3 centre (0, 183.9) radius 2
  concentric A3 C3
  dimension "d1685" diameter C3 = 4
extrude "Estrusione27" cut sketch "Schizzo25" profile of C3 against normal blind 4
component_from_bodies "Corpo->Comp1"
mirror "Specchio1" mirrorStitchTolerance 0.1
sketch "Schizzo8" plane through (-4, 0, 0) normal (1, 0, 0) x axis (0, 1, 0)
  circle C1 centre (0, 183.9) radius 2
extrude "Estrusione1" add of existing geometry blind 4
sketch "Schizzo1" plane through (0, 0, 0) normal (1, 0, 0) x axis (0, 1, 0)
  line L1 (-88.4, 164.9) -> (-88.4, 163.1)
  curve K1 (-88.3168, 169.8415) -> (-88.4, 164.9)
  curve K2 (-81.9366, 174.4086) -> (-88.3168, 169.8415)
  curve K3 (-69.9527, 188.2187) -> (-74.509, 181.8379)
  curve K4 (-65, 188.3) -> (-69.9527, 188.2187)
  line L2 (-10.9836, 188.3) -> (-65, 188.3)
  line L3 (65, 188.3) -> (10.9836, 188.3)
  curve K5 (65, 188.3) -> (69.9527, 188.2187)
  curve K6 (69.9527, 188.2187) -> (74.509, 181.8379)
  curve K7 (81.9366, 174.4086) -> (88.3168, 169.8415)
  curve K8 (88.3168, 169.8415) -> (88.4, 164.9)
  line L4 (88.4, 163.1) -> (88.4, 164.9)
  line L5 (86.4, 157.1) -> (86.4, 163.1)
  line L6 (88.2, 157.1) -> (86.4, 157.1)
  line L7 (88.2, 159.9) -> (88.2, 157.1)
  line L8 (90, 159.9) -> (88.2, 159.9)
  line L9 (90, 164.9) -> (90, 159.9)
  curve K9 (90, 164.9) -> (65, 189.9)
  line L10 (-65, 189.9) -> (65, 189.9)
  curve K10 (-90, 164.9) -> (-65, 189.9)
  line L11 (-90, 159.9) -> (-90, 164.9)
  line L12 (-88.2, 159.9) -> (-90, 159.9)
  line L13 (-88.2, 157.1) -> (-88.2, 159.9)
  line L14 (-86.4, 157.1) -> (-88.2, 157.1)
  line L15 (-86.4, 163.1) -> (-86.4, 157.1)
  line L16 (86.4, 163.1) -> (88.4, 163.1)
  line L17 (-88.4, 163.1) -> (-86.4, 163.1)
  arc A1 centre (-80.2735, 180.1735) radius 6 clockwise from (-74.509, 181.8379) to (-81.9366, 174.4086)
  arc A2 centre (-10.9836, 183.3) radius 5 clockwise from (-10.9836, 188.3) to (-5.9911, 183.5727)
  arc A3 centre (0, 183.9) radius 6 clockwise from (5.9911, 183.5727) to (-5.9911, 183.5727)
  arc A4 centre (10.9836, 183.3) radius 5 clockwise from (5.9911, 183.5727) to (10.9836, 188.3)
  arc A5 centre (80.2735, 180.1735) radius 6 clockwise from (81.9366, 174.4086) to (74.509, 181.8379)
  circle C1 centre (0, 183.9) radius 1.75
  circle C2 centre (80.2735, 180.1735) radius 1.75
  circle C3 centre (-80.2735, 180.1735) radius 1.75
  concentric A3 C1
  concentric A5 C2
  concentric A1 C3
  dimension "d1692" diameter C1 = 3.5
  dimension "d1693" diameter C2 = 3.5
  dimension "d1694" diameter C3 = 3.5
extrude "Estrusione2" cut sketch "Schizzo1" profile of C1 C2 C3 against normal blind 21.755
